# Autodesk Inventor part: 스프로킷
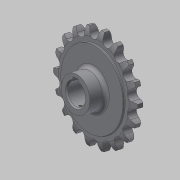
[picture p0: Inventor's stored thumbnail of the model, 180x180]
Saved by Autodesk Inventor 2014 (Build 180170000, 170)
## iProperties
Created: 2016-03
Part Number: 스프로킷
Material: 강철, 탄소
Document SubType Name: Modeling
Designer: mduedu
Density: 7.87 g/cm^3
Mass: 301.818 g
Surface Area: 124.882 cm^2
Volume: 38.3505 cm^3
Appearance: 반광택
Author: mduedu
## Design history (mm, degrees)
sketch "스케치1"
  geometry: L1 (0, 5)-(29.5, 5); L2 (29.5, 5)-(29.5, 4.1); L3 (30, 3.6)-(33.625, 3.6); L4 (40, 2)-(40, 0); L5 (40, 0)-(0, 0); L6 (0, 0)-(0, 5); L7 (0, -5)-(29.5, -5); L8 (29.5, -5)-(29.5, -4.1); L9 (30, -3.6)-(33.625, -3.6); L10 (40, -2)-(40, 0); L11 (0, 0)-(0, -5); A1 r 13.5 centre (33.625, -9.9) between (40, 2) and (33.625, 3.6); A2 r 13.5 centre (33.625, 9.9) between (33.625, -3.6) and (40, -2); A3 r 0.5 centre (30, 4.1) between (29.5, 4.1) and (30, 3.6); A4 r 0.5 centre (30, -4.1) between (30, -3.6) and (29.5, -4.1); 2 further points
  constraints: 22 end point, 8 point on circle, 6 symmetric about line, 5 tangent, 4 centre point, 4 parallel, 4 point on line, 1 equal radius, 1 horizontal, 1 perpendicular, 1 other
  dimensions: "d0" = 80 diameter of L4 L6; "d2" = 59 diameter of L2 L6; "d3" = 1.6 vertical distance of L4.start L3.end; "d4" = 3.6 distance from line of L4.end L3; "d5" = 5 distance between parallel lines of L5 L1; "d6" = 13.5 radius of A1; "d15" = 0.5 radius of A3
revolve "회전1" sketch "스케치1" stored, may be unused: angle "d7" = 90 deg
sketch "스케치2" dims "d8" = 65.2, "d11" = 80
  geometry: L1 (0, 0)-(0, 32.6); A1 r 36.57 centre (0, 0) between (-16.231, 32.771) and (0, 36.57); A2 r 3.97 centre (0, 36.57) between (-3.866, 35.665) and (0, 32.6); A3 r 12.7 centre (-16.231, 32.771) between (-3.866, 35.665) and (-5.534, 39.615); A4 r 12.7 centre (16.231, 32.771) between (5.534, 39.615) and (3.866, 35.665); A5 r 3.97 centre (0, 36.57) between (0, 32.6) and (3.866, 35.665); A6 r 40 centre (0, 0) between (5.534, 39.615) and (-5.534, 39.615); 2 further points
  constraints: 12 point on circle, 6 centre point, 4 coincident, 3 symmetric about line, 2 end point, 1 point on line, 1 tangent, 1 vertical, 1 vertical alignment, 7 other
  dimensions: "d10" = 73.14 diameter of A1; "d12" = 12.7 radius of A3
extrude "돌출1" cut sketch "스케치2" stored distance "d13" = 10; taper "d14" = 0 deg
sketch "스케치3"
  geometry: C1 r 13.5 at (0, 0); 1 further point
  constraints: 1 centre point, 1 coincident
  dimensions: "d19" = 27 diameter of C1
extrude "돌출2" join sketch "스케치3" distance "d20" = 13; taper "d21" = 0 deg
fillet "모깎기1" dims "d22" = 3
sketch "스케치4"
  geometry: L1 (-2.5, 0)-(2.5, 0); L2 (2.5, 0)-(2.5, 10.8); L3 (2.5, 10.8)-(-2.5, 10.8); L4 (-2.5, 10.8)-(-2.5, 0); C1 r 8.5 at (0, 0); 2 further points
  constraints: 8 end point, 2 coincident, 2 parallel, 1 centre point, 1 horizontal, 1 midpoint, 1 perpendicular
  dimensions: "d23" = 17 diameter of C1; "d25" = 5 distance of L2.end L3.end; "d26" = 10.8 distance of L1.end L2.end
extrude "돌출3" cut sketch "스케치4" stored distance "d27" = 8; taper "d28" = 0 deg
chamfer "모따기1" distance "d29" = 1; stored, may be unused: second distance "d30" = 2, angle "d31" = 45 deg
node "작업 평면1"
sketch "스케치5"
  geometry: L1 (13.5, 13)-(-13.5, 13) reference; 2 further points
  constraints: 1 vertical alignment
  dimensions: "d32" = 4 distance from line of point (0, 9) L1
hole "구멍1" sketch "스케치5" at (0, 9) diameter "d33" = 2.459; stored, may be unused: countersink angle "d37" = 90 deg, drill point angle "d39" = 118 deg; dims "d34" = 6, "d35" = 4, "d36" = 2, "d38" = 8
node "솔리드1"
pattern_circular "원형 패턴1" dims angle "d17" = 360 deg
